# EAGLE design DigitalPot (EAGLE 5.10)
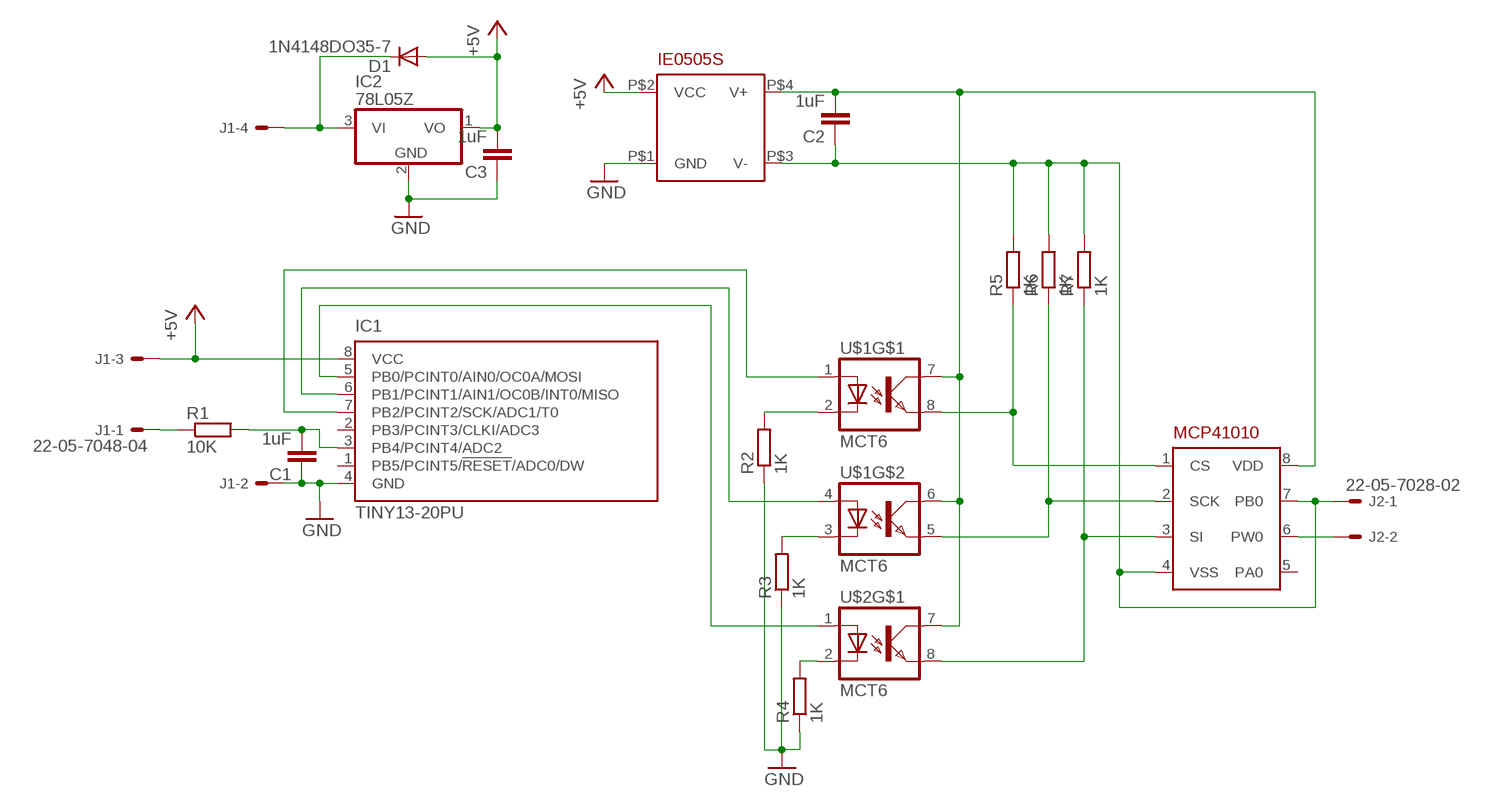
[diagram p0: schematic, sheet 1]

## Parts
C1  1uF  C-EU025-025X050  [C025-025X050]
C2  1uF  C-EU025-025X050  [C025-025X050]
C3  1uF  C-EU025-025X050  [C025-025X050]
D1  1N4148DO35-7  [DO35-7]
IC1  TINY13-20PU  [DIL08]
IC2  78L05Z  [TO92]
IE0505S  IE0505S  [SIL04]
J1  22-05-7048-04  [7395-04]
J2  22-05-7028-02  [7395-02]
MCP41010  MCP41010  [DIL08]
R1  10K  R-EU_0204/7  [0204/7]
R2  1K  R-EU_0204/7  [0204/7]
R3  1K  R-EU_0204/7  [0204/7]
R4  1K  R-EU_0204/7  [0204/7]
R5  1K  R-EU_0204/7  [0204/7]
R6  1K  R-EU_0204/7  [0204/7]
R7  1K  R-EU_0204/7  [0204/7]
U$1  MCT6  [DIL08]
U$2  MCT6  [DIL08]

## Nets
+5V: C3.2 D1.A IC1.8(VCC) IC2.1(VO) IE0505S.P$2(VCC) J1.3
GND: C1.1 C3.1 IC1.4(GND) IC2.2(GND) IE0505S.P$1(GND) J1.2 R2.1 R3.1 R4.1
N$2: J2.2 MCP41010.6(PW0)
N$3: D1.C IC2.3(VI) J1.4
N$5: C1.2 IC1.3(PB4/PCINT4/ADC2) R1.2
N$6: J1.1 R1.1
N$8: IC1.5(PB0/PCINT0/AIN0/OC0A/MOSI) U$2.1(A)
N$9: IC1.6(PB1/PCINT1/AIN1/OC0B/INT0/MISO) U$1.4(A)
N$10: IC1.7(PB2/PCINT2/SCK/ADC1/T0) U$1.1(A)
N$11: R4.2 U$2.2(C)
N$12: R3.2 U$1.3(C)
N$13: R2.2 U$1.2(C)
N$17: MCP41010.1(CS) R5.1 U$1.8(EMI)
N$18: MCP41010.2(SCK) R6.1 U$1.5(EMI)
N$19: MCP41010.3(SI) R7.1 U$2.8(EMI)
N$24: C2.2 IE0505S.P$4(V+) MCP41010.8(VDD) U$1.6(COL) U$1.7(COL) U$2.7(COL)
V-: C2.1 IE0505S.P$3(V-) J2.1 MCP41010.4(VSS) MCP41010.7(PB0) R5.2 R6.2 R7.2
Unconnected: IC1.1(PB5/PCINT5/!RESET!/ADC0/DW) IC1.2(PB3/PCINT3/CLKI/ADC3) MCP41010.5(PA0) U$2.3(C) U$2.4(A) U$2.5(EMI) U$2.6(COL)

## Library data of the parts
C1-C3 = resistor:C-EU: CAPACITOR, European symbol
D1 = diode:1N4148: DIODE
IC1 = atmel:TINY13: 8-bit AVR Microcontroller with 1K Bytes In-System Programmable Flash Source: http://www.atmel.com/dyn/resources/prod_documents/2535S.pdf
IC2 = linear:78*: Positive VOLTAGE REGULATOR Source: http://cache.national.com/ds/LM/LM78L05.pdf http://www.fairchildsemi.com/ds/LM/LM7805.pdf
IE0505S = Ians parts:IE0505S
J1 = con-molex:22-?-04: CONNECTOR wire to board 2.54 mm (.1 inch) pitch header
J2 = con-molex:22-?-02: CONNECTOR
MCP41010 = Ians parts:MCP41010
R1-R7 = resistor:R-EU_: RESISTOR, European symbol
U$1 U$2 = Ians parts:MCT6

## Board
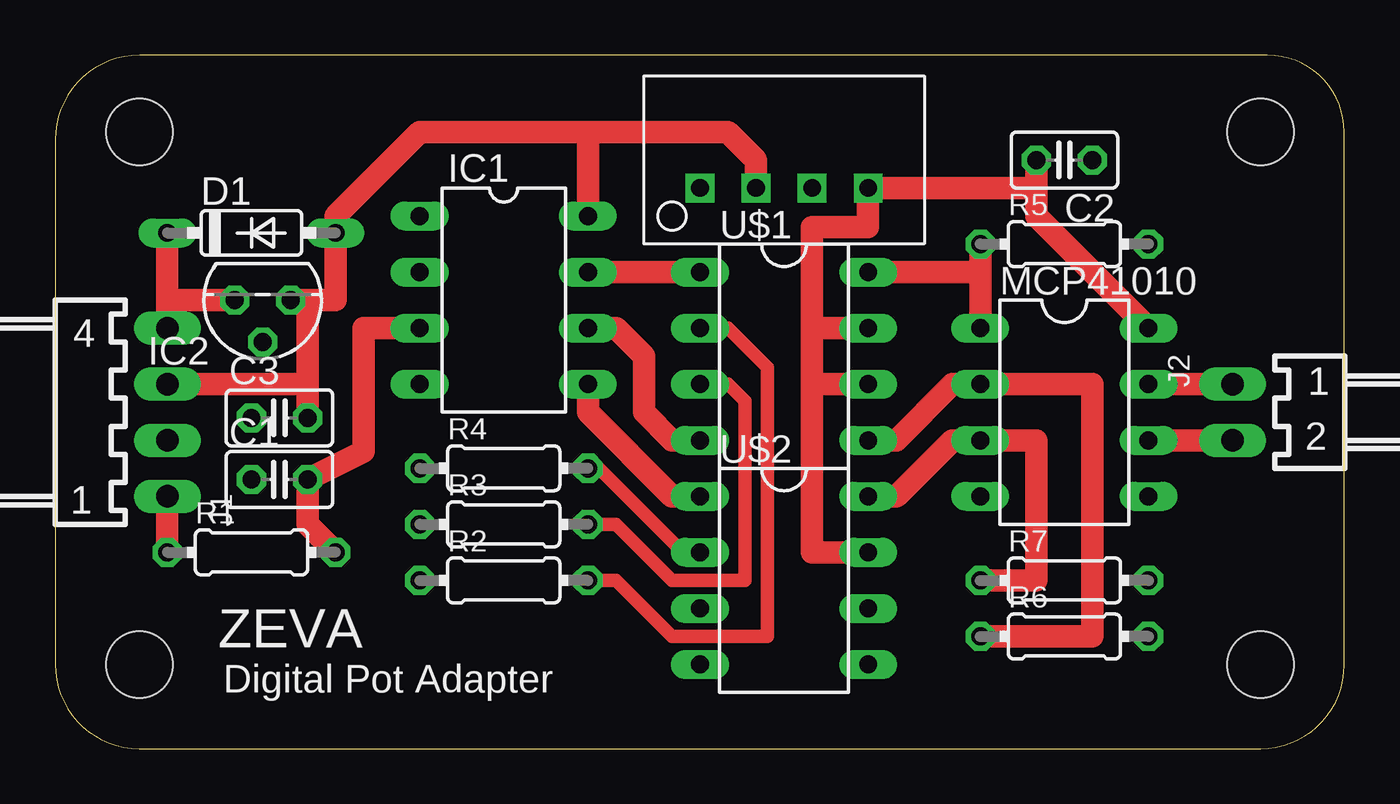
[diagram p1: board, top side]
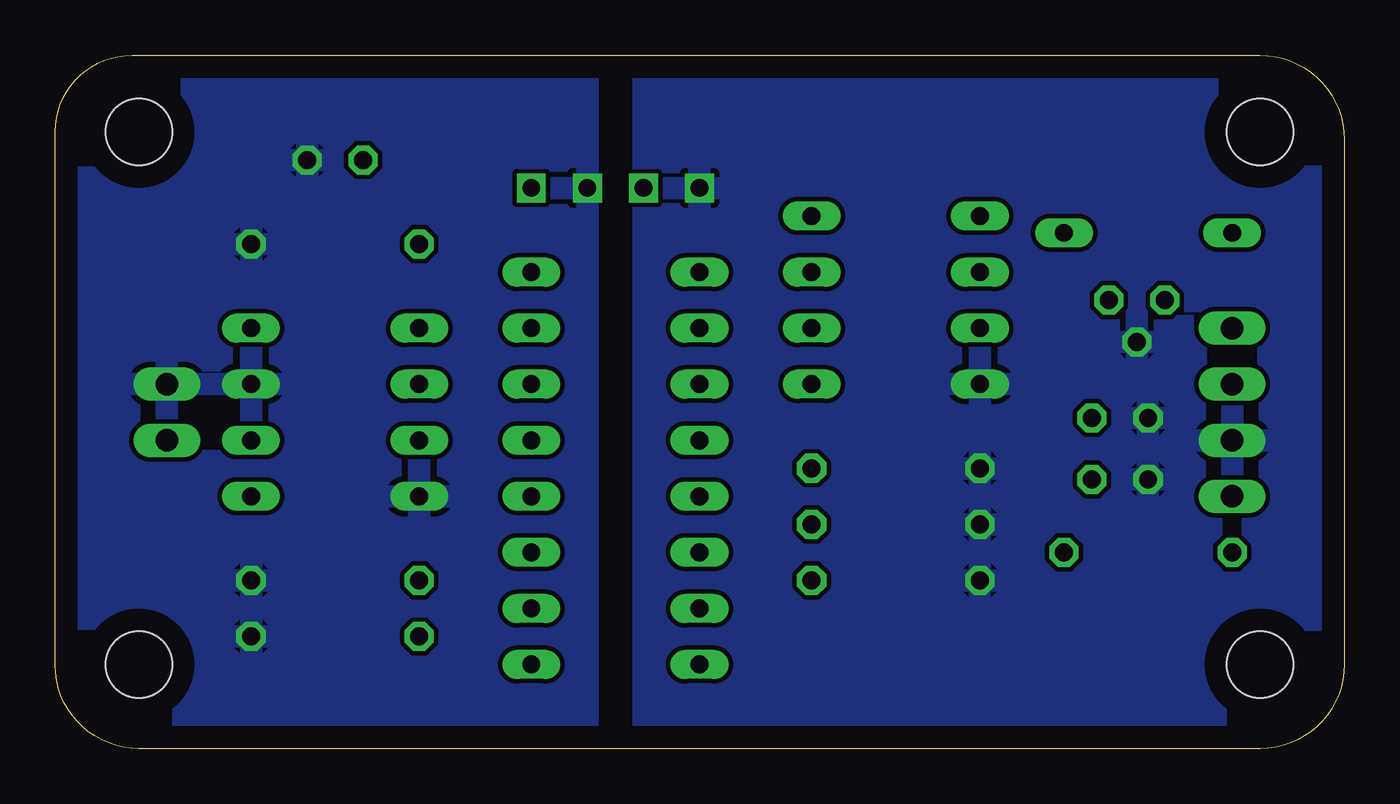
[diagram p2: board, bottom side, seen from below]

Size 58.4 x 31.42 mm. Coordinates in mm from the lower left corner, seen from the top.
Outline: 3.82,31.42 arc90 0,27.6 0,3.81 arc90 3.81,0 54.61,0 arc90 58.4,3.79 58.4,27.94 arc90 54.92,31.42 3.82,31.42
Copper layers (1*16): Top 0.035mm / dielectric 1.5mm / Bottom 0.035mm
Design rules "default": minimum track width 10mil, minimum drill 24mil, track to track 8mil, track to pad 8mil, pad to pad 8mil, via to via 8mil, smd to smd 8mil, copper to edge 40mil, drill to drill 8mil, minimum pad ring 10mil, minimum via ring 8mil, stop-mask expansion 4mil, vias tented up to drill 0mil, thermal gap 10mil
Holes 3 mm at 3.81,3.81 3.81,27.94 54.61,27.94 54.61,3.81

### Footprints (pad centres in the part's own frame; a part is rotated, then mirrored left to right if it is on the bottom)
C025-025X050 = drill 0.813 octagon: 1 -1.27,0; 2 1.27,0
DO35-7 = drill 0.813 long: A 3.81,0; C -3.81,0
DIL08 = drill 0.813 long: 1 -3.81,-3.81; 2 -1.27,-3.81; 3 1.27,-3.81; 4 3.81,-3.81; 5 3.81,3.81; 6 1.27,3.81; 7 -1.27,3.81; 8 -3.81,3.81
TO92 = drill 0.813 octagon: 1 -1.27,0; 2 0,1.905; 3 1.27,0
SIL04 = drill 0.8 square: P$1 0,3.81; P$2 0,1.27; P$3 0,-1.27; P$4 0,-3.81
7395-04 = drill 1.016 long: 1 3.81,0; 2 1.27,0; 3 -1.27,0; 4 -3.81,0
7395-02 = drill 1.016 long: 1 1.27,0; 2 -1.27,0
0204/7 = drill 0.813 octagon: 1 -3.81,0; 2 3.81,0

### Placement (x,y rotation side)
C1  10.16,12.19 0 top
C2  45.72,26.67 180 top
C3  10.16,14.99 0 top
D1  8.89,23.37 0 top
IC1  20.32,20.32 270 top
IC2  9.4,20.32 180 top
IE0505S  33.02,25.4 90 top
J1  5.08,15.24 270 top
J2  53.34,15.24 90 top
MCP41010  45.72,15.24 270 top
R1  8.89,8.89 0 top
R2  20.32,7.62 0 top
R3  20.32,10.16 0 top
R4  20.32,12.7 0 top
R5  45.72,22.86 0 top
R6  45.72,5.08 0 top
R7  45.72,7.62 0 top
U$1  33.02,17.78 270 top
U$2  33.02,7.62 270 top

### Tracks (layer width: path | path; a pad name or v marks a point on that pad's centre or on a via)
+5V
  Top 1.016: 11.43,16.51 C3.2 | J1.3 11.43,16.51 | 11.43,20.32 IC2.1 | 11.43,20.32 12.7,20.32 D1.A 12.7,24.13 16.51,27.94 24.13,27.94 | 11.43,16.51 11.43,20.32 | 24.13,27.94 30.48,27.94 31.75,26.67 IE0505S.P$2 | 24.13,27.94 IC1.8
GND
  pour Bottom: -1.27,-1.27 31.75,-1.27 31.75,33.02 0,33.02
N$2
  Top 1.016: MCP41010.6 J2.2
N$3
  Top 1.016: J1.4 5.08,20.32 | 5.08,20.32 D1.C | 5.08,20.32 IC2.3
N$5
  Top 1.016: IC1.3 13.97,19.05 13.97,13.46 C1.2 11.43,10.16 R1.2
N$6
  Top 1.016: R1.1 J1.1
N$8
  Top 1.016: IC1.5 24.13,15.24 27.94,11.43 U$2.1
N$9
  Top 1.016: IC1.6 25.4,19.05 26.67,17.78 26.67,15.24 27.94,13.97 U$1.4
N$10
  Top 1.016: IC1.7 U$1.1
N$11
  Top 0.61: U$2.2 28.45,8.89 24.64,12.7 R4.2
N$12
  Top 0.61: U$1.3 30.48,16.51 31.24,15.75 31.24,7.62 27.94,7.62 25.4,10.16 R3.2
N$13
  Top 0.61: U$1.2 30.48,19.05 32.26,17.27 32.26,5.08 27.94,5.08 25.4,7.62 R2.2
N$17
  Top 1.016: 41.91,21.59 MCP41010.1 | 41.91,21.59 R5.1 | U$1.8 41.91,21.59
N$18
  Top 1.016: R6.1 46.99,5.08 46.99,16.51 MCP41010.2 40.64,16.51 38.1,13.97 U$1.5
N$19
  Top 1.016: R7.1 44.45,7.62 44.45,13.97 MCP41010.3 40.64,13.97 38.1,11.43 U$2.8
N$24
  Top 1.016: 34.29,16.51 34.29,19.05 | 34.29,16.51 U$1.6 | 34.29,16.51 34.29,8.89 U$2.7 | 34.29,19.05 34.29,23.62 36.83,23.62 IE0505S.P$4 44.45,25.4 C2.2 44.45,24.13 MCP41010.8 | 34.29,19.05 U$1.7
V-
  Top 1.016: MCP41010.7 J2.1
  pour Bottom: 34.29,33.02 59.69,33.02 59.69,-1.27 34.29,-1.27

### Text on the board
tPlace: ZEVA | Digital Pot Adapter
